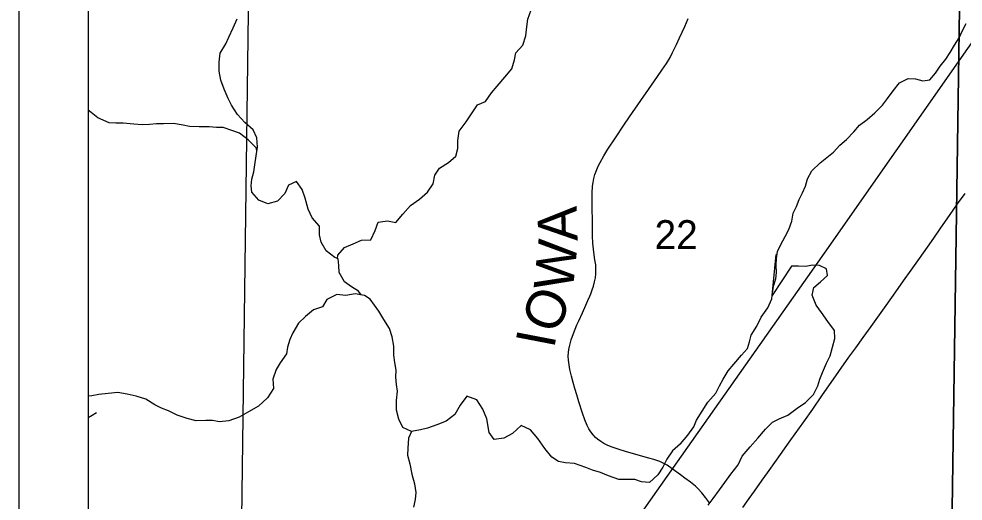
# Model space of a CAD drawing. Extents: x 0 to 34, y 0 to 22.
# Drawn here: x 2 to 3.363, y 17.725 to 18.422 of the extents above; entities that cross this region are included whole.
import ezdxf

# ---------------------------------------------------------------- set-up
doc = ezdxf.new("R2010")
doc.units = 0
for name, color, linetype in [('GM_X_Corporation', 7, 'Continuous'), ('GM_X_Minor_River', 7, 'Continuous'), ('GM_X_Rail_Line', 7, 'Continuous'), ('GM_X_Section_Text', 7, 'Continuous'), ('GM_X_State_Route', 7, 'Continuous'), ('GM_X_Township_Road', 7, 'Continuous'), ('GM_X_Township_Road_Text', 7, 'Continuous'), ('SH_Data', 7, 'Continuous')]:
    doc.layers.add(name, color=color, linetype=linetype)

msp = doc.modelspace()

# ---------------------------------------------------------------- linework, layer by layer
at = {"layer": 'GM_X_Corporation'}
for points in [[(8.9, 20.9), (2.1, 20.9), (2.1, 15.6606)], [(5.3543, 16.3597), (5.3699, 17.5116), (5.3717, 17.6123), (4.6401, 17.6298), (4.3705, 17.6391), (4.3669, 17.8198), (4.37, 17.9048), (4.3768, 18.4091), (4.3782, 18.6502), (4.377, 18.6713), (3.7035, 18.69), (3.3642, 18.7005), (3.3691, 19.5041), (3.3724, 19.7263), (3.3869, 20.7918), (3.3886, 20.9), (2.1, 20.9), (2.1, 15.6606)]]:
    msp.add_lwpolyline(points, dxfattribs=at)
for points in [[(2.1, 18.7299), (2.1, 17.7065), (2.3219, 17.7003), (2.3352, 18.7231)], [(2.3352, 18.7231), (3.3614, 18.7006), (3.3465, 17.6805), (2.3219, 17.7003)], [(4.3772, 18.6714), (4.3675, 17.6365), (3.3465, 17.6805), (3.3614, 18.7006)]]:
    msp.add_lwpolyline(points, close=True, dxfattribs=at)
at = {"layer": 'GM_X_Minor_River'}
for points in [[(2.4597, 18.0754), (2.4605, 18.0801), (2.4699, 18.0912), (2.4824, 18.0966), (2.4945, 18.102), (2.5081, 18.1025), (2.5145, 18.1158), (2.5185, 18.128), (2.5322, 18.1299), (2.5443, 18.1274), (2.5541, 18.1396), (2.5654, 18.1522), (2.5782, 18.161), (2.5899, 18.1713), (2.5982, 18.1835), (2.6004, 18.1961), (2.6071, 18.206), (2.6199, 18.2144), (2.6309, 18.2232), (2.6335, 18.2343), (2.6334, 18.246), (2.6356, 18.2593), (2.6457, 18.2727), (2.6532, 18.2845), (2.6622, 18.2975), (2.6736, 18.3021), (2.6822, 18.3147), (2.6905, 18.3246), (2.7014, 18.3376), (2.7115, 18.3494), (2.7156, 18.3623), (2.7174, 18.3726), (2.7272, 18.3837), (2.7317, 18.3974), (2.7331, 18.4103), (2.7345, 18.4213), (2.7394, 18.4346)], [(2.4609, 18.0748), (2.456, 18.077), (2.4434, 18.0868), (2.4361, 18.0993), (2.4341, 18.1095), (2.434, 18.1224), (2.4233, 18.1341), (2.4176, 18.147), (2.4133, 18.1625), (2.4087, 18.1754), (2.4006, 18.1867), (2.3893, 18.1814), (2.3841, 18.1696), (2.3735, 18.1585), (2.3595, 18.1546), (2.3466, 18.1598), (2.3363, 18.1711), (2.3351, 18.1806), (2.3361, 18.1901), (2.3391, 18.2008), (2.3406, 18.2106), (2.3424, 18.2236), (2.3442, 18.2361), (2.3433, 18.2497), (2.3383, 18.2615), (2.3261, 18.272), (2.3158, 18.2837), (2.307, 18.2969), (2.302, 18.3068), (2.2962, 18.32), (2.2916, 18.3333), (2.2892, 18.3462), (2.2891, 18.3591), (2.2906, 18.372), (2.2988, 18.3857), (2.3029, 18.3952), (2.3093, 18.4089), (2.3152, 18.4219)], [(3.0872, 18.022), (3.0893, 18.0357), (3.0926, 18.046), (3.0936, 18.0554), (3.0932, 18.066), (3.0935, 18.0755), (3.0949, 18.0854), (3.0993, 18.0949), (3.106, 18.1075), (3.1112, 18.1174), (3.1157, 18.1295), (3.1178, 18.1409), (3.1223, 18.1508), (3.1264, 18.1607), (3.1312, 18.1702), (3.1353, 18.1801), (3.1382, 18.1904), (3.1445, 18.2022), (3.1565, 18.2137), (3.176, 18.2291), (3.185, 18.239), (3.1948, 18.2474), (3.2053, 18.2585), (3.2135, 18.2681), (3.2244, 18.2765), (3.2357, 18.2858), (3.2465, 18.2969), (3.2536, 18.3068), (3.2622, 18.3179), (3.2712, 18.3293), (3.2836, 18.3355), (3.2942, 18.3349), (3.3048, 18.3323), (3.315, 18.3336), (3.3232, 18.3431), (3.33, 18.3534), (3.3382, 18.3634), (3.3445, 18.3733), (3.3505, 18.3836), (3.3572, 18.3942), (3.362, 18.4049), (3.3672, 18.4152)], [(2.3435, 18.2314), (2.3423, 18.2353), (2.3312, 18.247), (2.3183, 18.2568), (2.3088, 18.2601), (2.2951, 18.2646), (2.2852, 18.2649), (2.2746, 18.2656), (2.2602, 18.2659), (2.2465, 18.2662), (2.237, 18.268), (2.223, 18.2706), (2.2086, 18.2701), (2.1987, 18.27), (2.1885, 18.2692), (2.1779, 18.2684), (2.1658, 18.2698), (2.1506, 18.2708), (2.14, 18.2711), (2.1301, 18.2715), (2.1138, 18.2789), (2.1042, 18.2865), (2.1, 18.2898)], [(2.4941, 18.0228), (2.4904, 18.0283), (2.4801, 18.0347), (2.4698, 18.0418), (2.4622, 18.0551), (2.4617, 18.0653), (2.4609, 18.0748)], [(3.1452, 18.0226), (3.1475, 18.0336), (3.1573, 18.0417), (3.167, 18.0509), (3.1658, 18.0607), (3.1556, 18.0652), (3.1457, 18.0658), (3.1359, 18.0638), (3.1253, 18.0645), (3.1151, 18.0644), (3.0872, 18.022), (3.093, 18.0812), (3.0938, 18.0801)], [(2.5071, 18.0166), (2.4988, 18.0219), (2.4855, 18.0245), (2.4719, 18.0221), (2.459, 18.0235), (2.4447, 18.0161)], [(2.9548, 17.8077), (2.9655, 17.8204), (2.9741, 17.8322), (2.9782, 17.8417), (2.9864, 17.8551), (2.9947, 17.868), (3.006, 17.881), (3.0112, 17.8913), (3.0168, 17.9012), (3.0236, 17.9134), (3.0318, 17.923), (3.0431, 17.9356), (3.0518, 17.9455), (3.0547, 17.955), (3.0569, 17.9649), (3.0652, 17.9775), (3.0715, 17.9908), (3.0809, 18.0042), (3.0869, 18.0171), (3.0872, 18.022)], [(2.995, 17.7189), (3.0021, 17.7288), (3.0115, 17.7414), (3.019, 17.7521), (3.0277, 17.764), (3.0382, 17.7773), (3.0442, 17.7899), (3.0554, 17.8033), (3.0667, 17.8159), (3.0776, 17.8289), (3.0878, 17.8388), (3.0976, 17.8438), (3.1101, 17.8492), (3.1236, 17.8592), (3.1353, 17.8673), (3.147, 17.8791), (3.1534, 17.8917), (3.156, 17.9012), (3.1601, 17.9107), (3.166, 17.9241), (3.1713, 17.9347), (3.1742, 17.9473), (3.1779, 17.9598), (3.1771, 17.9716), (3.1679, 17.9844), (3.1587, 17.9976), (3.151, 18.0082), (3.1452, 18.0226)], [(2.4447, 18.0161), (2.4384, 18.0058), (2.4255, 18.0015), (2.4135, 17.9915), (2.4038, 17.9819), (2.3952, 17.9682), (2.3911, 17.9587), (2.3879, 17.9473), (2.3861, 17.9378), (2.3771, 17.9248), (2.3712, 17.9153), (2.3668, 17.9012), (2.3673, 17.8875), (2.3591, 17.8742), (2.346, 17.8623), (2.3313, 17.8538), (2.3181, 17.8461), (2.303, 17.841), (2.2898, 17.8397), (2.2796, 17.8415), (2.2697, 17.8414), (2.2561, 17.8409), (2.2428, 17.8442), (2.2284, 17.8493), (2.2158, 17.8552), (2.206, 17.8593), (2.1961, 17.8641), (2.1831, 17.8723), (2.1691, 17.8767), (2.1562, 17.8796), (2.1429, 17.8818), (2.1289, 17.8805), (2.1153, 17.8792), (2.1055, 17.8772), (2.1, 17.8768)], [(2.9544, 17.8073), (2.9548, 17.8077), (2.9435, 17.7977), (2.9353, 17.7858), (2.9297, 17.774), (2.9223, 17.763), (2.9103, 17.7518), (2.8989, 17.7529), (2.889, 17.7562), (2.8777, 17.7564), (2.866, 17.7563), (2.8511, 17.7615), (2.8394, 17.7663), (2.828, 17.7696), (2.8185, 17.7736), (2.8021, 17.7795), (2.7889, 17.7805), (2.779, 17.7823), (2.7691, 17.7883), (2.7591, 17.8011), (2.7492, 17.8154), (2.7384, 17.8281), (2.7251, 17.8341), (2.7127, 17.8229), (2.6999, 17.816), (2.686, 17.8139), (2.6787, 17.8241), (2.6754, 17.8438), (2.6696, 17.8577), (2.6608, 17.8713), (2.6467, 17.8764), (2.637, 17.8635), (2.6292, 17.8501), (2.6168, 17.8405), (2.6032, 17.835), (2.59, 17.8304), (2.5795, 17.828), (2.5666, 17.8256), (2.5541, 17.8311), (2.5483, 17.8436), (2.5451, 17.8564), (2.5453, 17.8705), (2.5463, 17.8837), (2.5451, 17.8936), (2.5442, 17.9042), (2.5445, 17.9144), (2.5425, 17.925), (2.5413, 17.9356), (2.5411, 17.9489), (2.5387, 17.9621), (2.5348, 17.9746), (2.5267, 17.9874), (2.5198, 17.9994), (2.5071, 18.0166)], [(2.5666, 17.8256), (2.5622, 17.8157), (2.5612, 17.8016), (2.5609, 17.7914), (2.5641, 17.7789), (2.5673, 17.7638), (2.5712, 17.7498), (2.5732, 17.7373), (2.5718, 17.7271), (2.5696, 17.7164)]]:
    msp.add_lwpolyline(points, dxfattribs=at)
at = {"layer": 'GM_X_Rail_Line'}
msp.add_lwpolyline([(3.6829, 18.8279), (3.1625, 18.0833), (2.66, 17.3693), (2.6227, 17.3226), (2.5817, 17.2815), (2.544, 17.2487), (2.292, 17.055), (2.1, 16.9029)], dxfattribs=at)
at = {"layer": 'GM_X_State_Route'}
msp.add_lwpolyline([(3.0452, 17.7156), (3.0543, 17.7289), (3.0618, 17.7395), (3.0728, 17.7552), (3.0804, 17.7658), (3.0936, 17.7839), (3.1143, 17.8134), (3.133, 17.8397), (3.1459, 17.858), (3.1589, 17.8769), (3.1835, 17.912), (3.1982, 17.9328), (3.208, 17.9465), (3.2185, 17.9612), (3.2301, 17.9773), (3.2518, 18.0075), (3.266, 18.0272), (3.277, 18.043), (3.2881, 18.0588), (3.3, 18.0755), (3.3115, 18.0917), (3.3208, 18.1049), (3.331, 18.1198), (3.3433, 18.1377), (3.3551, 18.1544), (3.366, 18.1695)], dxfattribs=at)
at = {"layer": 'GM_X_Township_Road'}
for points in [[(2.997, 17.7223), (2.9911, 17.7303), (2.9856, 17.7371), (2.9801, 17.743), (2.9765, 17.7464), (2.9693, 17.7523), (2.9614, 17.7582), (2.9548, 17.7628), (2.9428, 17.7716), (2.9357, 17.7767), (2.9309, 17.7795), (2.9252, 17.782), (2.9164, 17.7849), (2.9092, 17.787), (2.8769, 17.7962), (2.865, 17.7998), (2.8562, 17.8028), (2.8499, 17.8055), (2.8444, 17.8083), (2.8401, 17.8109), (2.8351, 17.8145), (2.8323, 17.817), (2.8289, 17.8205), (2.8255, 17.825), (2.8229, 17.8293), (2.8204, 17.8342), (2.8171, 17.8423), (2.8135, 17.8522), (2.8083, 17.8682), (2.8052, 17.8783), (2.8025, 17.8878), (2.8002, 17.8962), (2.7979, 17.9057), (2.7955, 17.9153), (2.7942, 17.922), (2.7933, 17.9287), (2.7931, 17.9342), (2.7933, 17.9398), (2.7939, 17.944), (2.7951, 17.9501), (2.7973, 17.9578), (2.8005, 17.9672), (2.8029, 17.9735), (2.8056, 17.9798), (2.8082, 17.9854), (2.8136, 17.9972), (2.8185, 18.008), (2.8215, 18.0148), (2.8242, 18.021), (2.8256, 18.0245), (2.8277, 18.0303), (2.8294, 18.0356), (2.831, 18.0416), (2.8322, 18.0477), (2.8328, 18.0532), (2.8329, 18.0601), (2.8326, 18.0663), (2.8316, 18.0736), (2.83, 18.0845), (2.8284, 18.0975), (2.8278, 18.1084), (2.8276, 18.1699), (2.8281, 18.1799), (2.8288, 18.1855), (2.8299, 18.1909), (2.8316, 18.1969), (2.8337, 18.2028), (2.8359, 18.2079), (2.8389, 18.214), (2.8445, 18.2237), (2.8503, 18.2333), (2.861, 18.25), (2.8732, 18.268), (2.8815, 18.2803), (2.8977, 18.3038), (2.9087, 18.3196), (2.9219, 18.3384), (2.9282, 18.3476), (2.9347, 18.3574), (2.9399, 18.3659), (2.9437, 18.373), (2.9494, 18.3847), (2.9538, 18.3943), (2.9613, 18.4107), (2.9662, 18.4221)], [(2.1, 17.8457), (2.1057, 17.8493), (2.1121, 17.8531)]]:
    msp.add_lwpolyline(points, dxfattribs=at)
at = {"layer": 'SH_Data'}
for p, q in [((2, 21), (2, 14)), ((2.1, 20.9), (2.1, 14.1))]:
    msp.add_line(p, q, dxfattribs=at)

# ---------------------------------------------------------------- texts
at = {"layer": 'GM_X_Section_Text'}
msp.add_text('22', height=0.04186, rotation=0, dxfattribs=at).set_placement((2.9176, 18.089))
at = {"layer": 'GM_X_Township_Road_Text'}
for s, rotation, p in [('A', 91.4742, (2.8065, 18.1011)), ('W', 84.1385, (2.7995, 18.0277)), ('O', 67.5438, (2.776, 17.9641)), ('I', 79.0996, (2.7724, 17.9441))]:
    msp.add_text(s, height=0.0568, rotation=rotation, dxfattribs=at).set_placement(p)

doc.saveas('drawing.dxf')
